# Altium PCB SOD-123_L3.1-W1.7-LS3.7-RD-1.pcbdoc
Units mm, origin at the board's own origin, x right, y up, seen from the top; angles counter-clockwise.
Board outline 17.4 x 15.42 mm, 2 copper layers (Top Layer, Bottom Layer), stack 0 mm thick; 1 components, 0 nets, 2 pads, 0 vias.
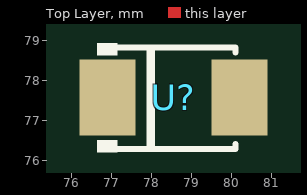
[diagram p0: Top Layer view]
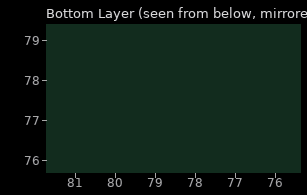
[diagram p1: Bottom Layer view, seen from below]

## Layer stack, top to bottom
Top Layer: signal copper (thickness not stored)
Bottom Layer: signal copper (thickness not stored)

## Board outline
87.25,69.85 69.85,69.85 69.85,85.27 87.25,85.27

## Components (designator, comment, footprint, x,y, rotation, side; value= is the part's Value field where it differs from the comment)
U? "" SOD-123_L3.1-W1.7-LS3.7-RD-1 78.55,77.57 r0 top

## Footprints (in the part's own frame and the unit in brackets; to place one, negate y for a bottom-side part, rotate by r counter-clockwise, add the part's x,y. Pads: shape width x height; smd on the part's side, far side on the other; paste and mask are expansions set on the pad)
SOD-123_L3.1-W1.7-LS3.7-RD-1 [mm]
  rect 1.4x1.9 smd: 1(-1.65,0) 2(1.65,0)
  silkscreen extent -1.91,-1.37 1.55,1.35

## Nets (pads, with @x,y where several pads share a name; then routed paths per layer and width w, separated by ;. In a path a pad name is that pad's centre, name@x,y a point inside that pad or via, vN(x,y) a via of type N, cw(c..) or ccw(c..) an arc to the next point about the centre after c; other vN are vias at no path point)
pads on no net: U?.1 U?.2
